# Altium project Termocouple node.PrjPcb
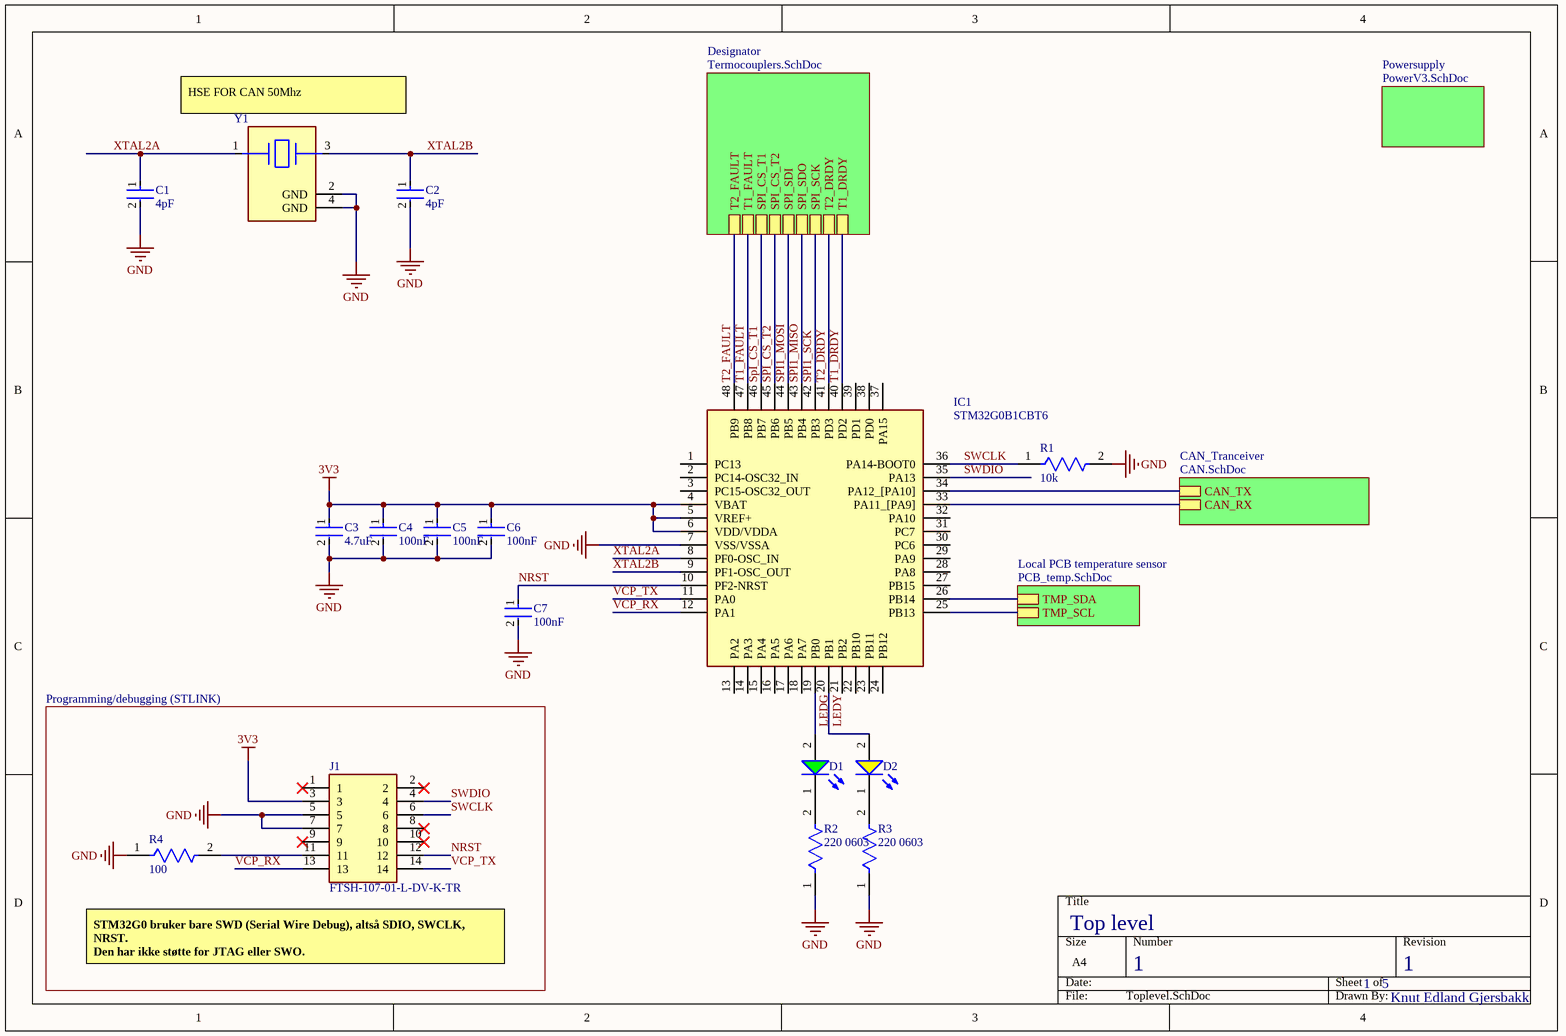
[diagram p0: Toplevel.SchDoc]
5 sheets, 64 parts. Net scope: hierarchical (ports join the sheet entries above them; power ports are global).
Board file: TermoCoupleNode.PcbDoc
Sheets:
  Toplevel.SchDoc
    Powersupply = PowerV3.SchDoc
    CAN_Tranceiver = CAN.SchDoc
    Designator = Termocouplers.SchDoc
    Local PCB temperature sensor = PCB_temp.SchDoc

## Sheet Toplevel.SchDoc
size A4; SheetNumber: 1; SheetTotal: 5

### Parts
C1  4pF  [FP-GQM187-0_15-IPC_B]
C2  4pF  [FP-GQM187-0_15-IPC_B]
C3  4.7uF  [FP-GCM21B-0_15-IPC_A]
C4  100nF  [FP-CL10-IPC_A]
C5  100nF  [FP-CL10-IPC_A]
C6  100nF  [FP-CL10-IPC_A]
C7  100nF  [FP-CL10-IPC_A]
D1  150060GS55040  [WL-SMCD_0603]  (value not drawn)
D2  150060YS75020  [WL-SMCW_0603_150060xx75020]  (value not drawn)
IC1  STM32G0B1CBT6  [QFP50P900X900X160-48N]
J1  FTSH-107-01-L-DV-K-TR  [FTSH10701LDVKTR]
R1  10k  [FP-RT0603-IPC_C]
R2  220 0603  [FP-AF0603-IPC_C]
R3  220 0603  [FP-AF0603-IPC_C]
R4  100  [FP-RT0603-MFG]
Y1  ABM10W-50.0000MHZ-4-B1U-T3  [FP-ABM10W-MFG]  (value not drawn)

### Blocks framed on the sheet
Programming/debugging (STLINK): J1 R4

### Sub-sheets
CAN_Tranceiver = CAN.SchDoc: CAN_TX, CAN_RX
Designator = Termocouplers.SchDoc: T1_FAULT, SPI_SDI, SPI_SDO, SPI_SCK, SPI_CS_T1, T2_DRDY, SPI_CS_T2, T2_FAULT, T1_DRDY
Local PCB temperature sensor = PCB_temp.SchDoc: TMP_SCL, TMP_SDA
Powersupply = PowerV3.SchDoc: no entries

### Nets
3V3: C3.1 C4.1 C5.1 C6.1 IC1.4(VBAT) IC1.5(VREF+) IC1.6(VDD/VDDA) J1.3
GND: C1.2 C2.2 C3.2 C4.2 C5.2 C6.2 C7.2 IC1.7(VSS/VSSA) J1.5 J1.7 R1.2 R2.1 R3.1 R4.1 Y1.2(GND) Y1.4(GND)
LEDG: D1.2(A) IC1.19(PB0)
LEDY: D2.2(A) IC1.20(PB1)
NRST: C7.1 IC1.10(PF2-NRST) J1.12
SCL: IC1.25(PB13) ; sheet Local PCB temperature sensor/TMP_SCL
SDA: IC1.26(PB14) ; sheet Local PCB temperature sensor/TMP_SDA
SPI1_MISO: IC1.43(PB4) ; sheet Designator/SPI_SDO
SPI1_MOSI: IC1.44(PB5) ; sheet Designator/SPI_SDI
SPI1_SCK: IC1.42(PB3) ; sheet Designator/SPI_SCK
SpI_CS_T1: IC1.46(PB7) ; sheet Designator/SPI_CS_T1
SPI_CS_T2: IC1.45(PB6) ; sheet Designator/SPI_CS_T2
SWCLK: IC1.36(PA14-BOOT0) J1.6 R1.1
SWDIO: IC1.35(PA13) J1.4
T1_DRDY: IC1.40(PD2) ; sheet Designator/T1_DRDY
T1_FAULT: IC1.47(PB8) ; sheet Designator/T1_FAULT
T2_DRDY: IC1.41(PD3) ; sheet Designator/T2_DRDY
T2_FAULT: IC1.48(PB9) ; sheet Designator/T2_FAULT
VCP_RX: IC1.12(PA1) J1.13
VCP_TX: IC1.11(PA0) J1.14
XTAL2A: C1.1 IC1.8(PF0-OSC_IN) Y1.1
XTAL2B: C2.1 IC1.9(PF1-OSC_OUT) Y1.3
NetD1_1: D1.1(K) R2.2
NetD2_1: D2.1(K) R3.2
NetIC1_33: IC1.33(PA11_[PA9]) ; sheet CAN_Tranceiver/CAN_RX
NetIC1_34: IC1.34(PA12_[PA10]) ; sheet CAN_Tranceiver/CAN_TX
NetJ1_11: J1.11 R4.2

Not connected (* = marked no-connect by the designer): IC1 1(PC13) 2(PC14-OSC32_IN) 3(PC15-OSC32_OUT) 13(PA2) 14(PA3) 15(PA4) 16(PA5) 17(PA6) 18(PA7) 21(PB2) 22(PB10) 23(PB11) 24(PB12) 27(PB15) 28(PA8) 29(PA9) 30(PC6) 31(PC7) 32(PA10) 37(PA15) 38(PD0) 39(PD1); J1 1* 2* 8* 9* 10*

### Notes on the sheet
- (near Y1) HSE FOR CAN 50Mhz
- Top level
- STM32G0 bruker bare SWD (Serial Wire Debug), altså SDIO, SWCLK, NRST.
  Den har ikke støtte for JTAG eller SWO.
- 1
- 5
- Knut Edland Gjersbakk

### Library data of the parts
C1 C2 = CMP-06035-061124-1: GQM1875C2E4R0BB12D / Ceramic Capacitor 4pF ±0.1pF 250VDC C0G 0603 Paper T/R; Voltage Rating: 250V
C3 = CMP-2007-03343-2: Ceramic Capacitor for Automotive 4.7uF ±10% 16VDC X7R 0805 Embossed T/R; Voltage Rating (DC): 16V
C4-C7 = CMP-13271-002683-1: Cap Ceramic 100nF 16V X7R ±10% Pad SMD 0603 +125°C T/R
D1 = CMP-03913-90235563-2: 150060GS55040 WL-SMCD SMT Mono-color Chip LED Diffused; Forward Voltage: 3.2V; Forward Current: 60mA; Luminous Intensity: 430mcd; Peak Wavelength: 520nm; Viewing Angle: 140°; Wavelength: 525nm; Max Reverse Voltage (DC): 5V
D2 = CMP-03913-104891429-2: WL-SMCW SMT Mono-Color Chip LED Waterclear super f; Forward Voltage: 2V; Forward Current: 60mA; Max Reverse Voltage (DC): 5V; Peak Wavelength: 595nm; Viewing Angle: 140°; Dominant Wavelength: 590nm; Luminous Intensity: 130mcd
IC1 = STM32G0B1CBT6: Integrated Circuit; Manufacturer_Name: STMicroelectronics
J1 = FTSH-107-01-L-DV-K-TR: Connector; Manufacturer_Name: SAMTEC
R1 = CMP-03412-005349-1: RES SMD 10K OHM 1% 1/10W 0603 / RT0603FRE0710KL; Manufacturer: Yageo; Value: 10KΩ; Temperature Coefficient: 50 ppm/°C; Power Rating: 0.1W; Tolerance: 0.01; Voltage Rating: 75V
R2 R3 = CMP-03412-038529-1: AF0603JR-07220RL Anti-Sulfurated Chip Resistors Automotive Grade 220Ω 5% 100ppm/°C 0603; Max Power Dissipation: 100mW; Resistance: 220R
R4 = CMP-03412-030646-1: RT0603 100Ω 0.1W 50 ppm/°C 1.00% RT0603FRE07100RL; Manufacturer: Yageo; Manufacturer Part Number: RT0603FRE10100RL; Tolerance: 0.01; Voltage Rating: 75V
Y1 = CMP-27762-007472-1: Crystal 50MHz ±10ppm 4pF SMD-4 2.5mm x 2mm; ESR (Equivalent Series Resistance): 70R

## Sheet PowerV3.SchDoc
size A3; SheetNumber: 3; SheetTotal: 5
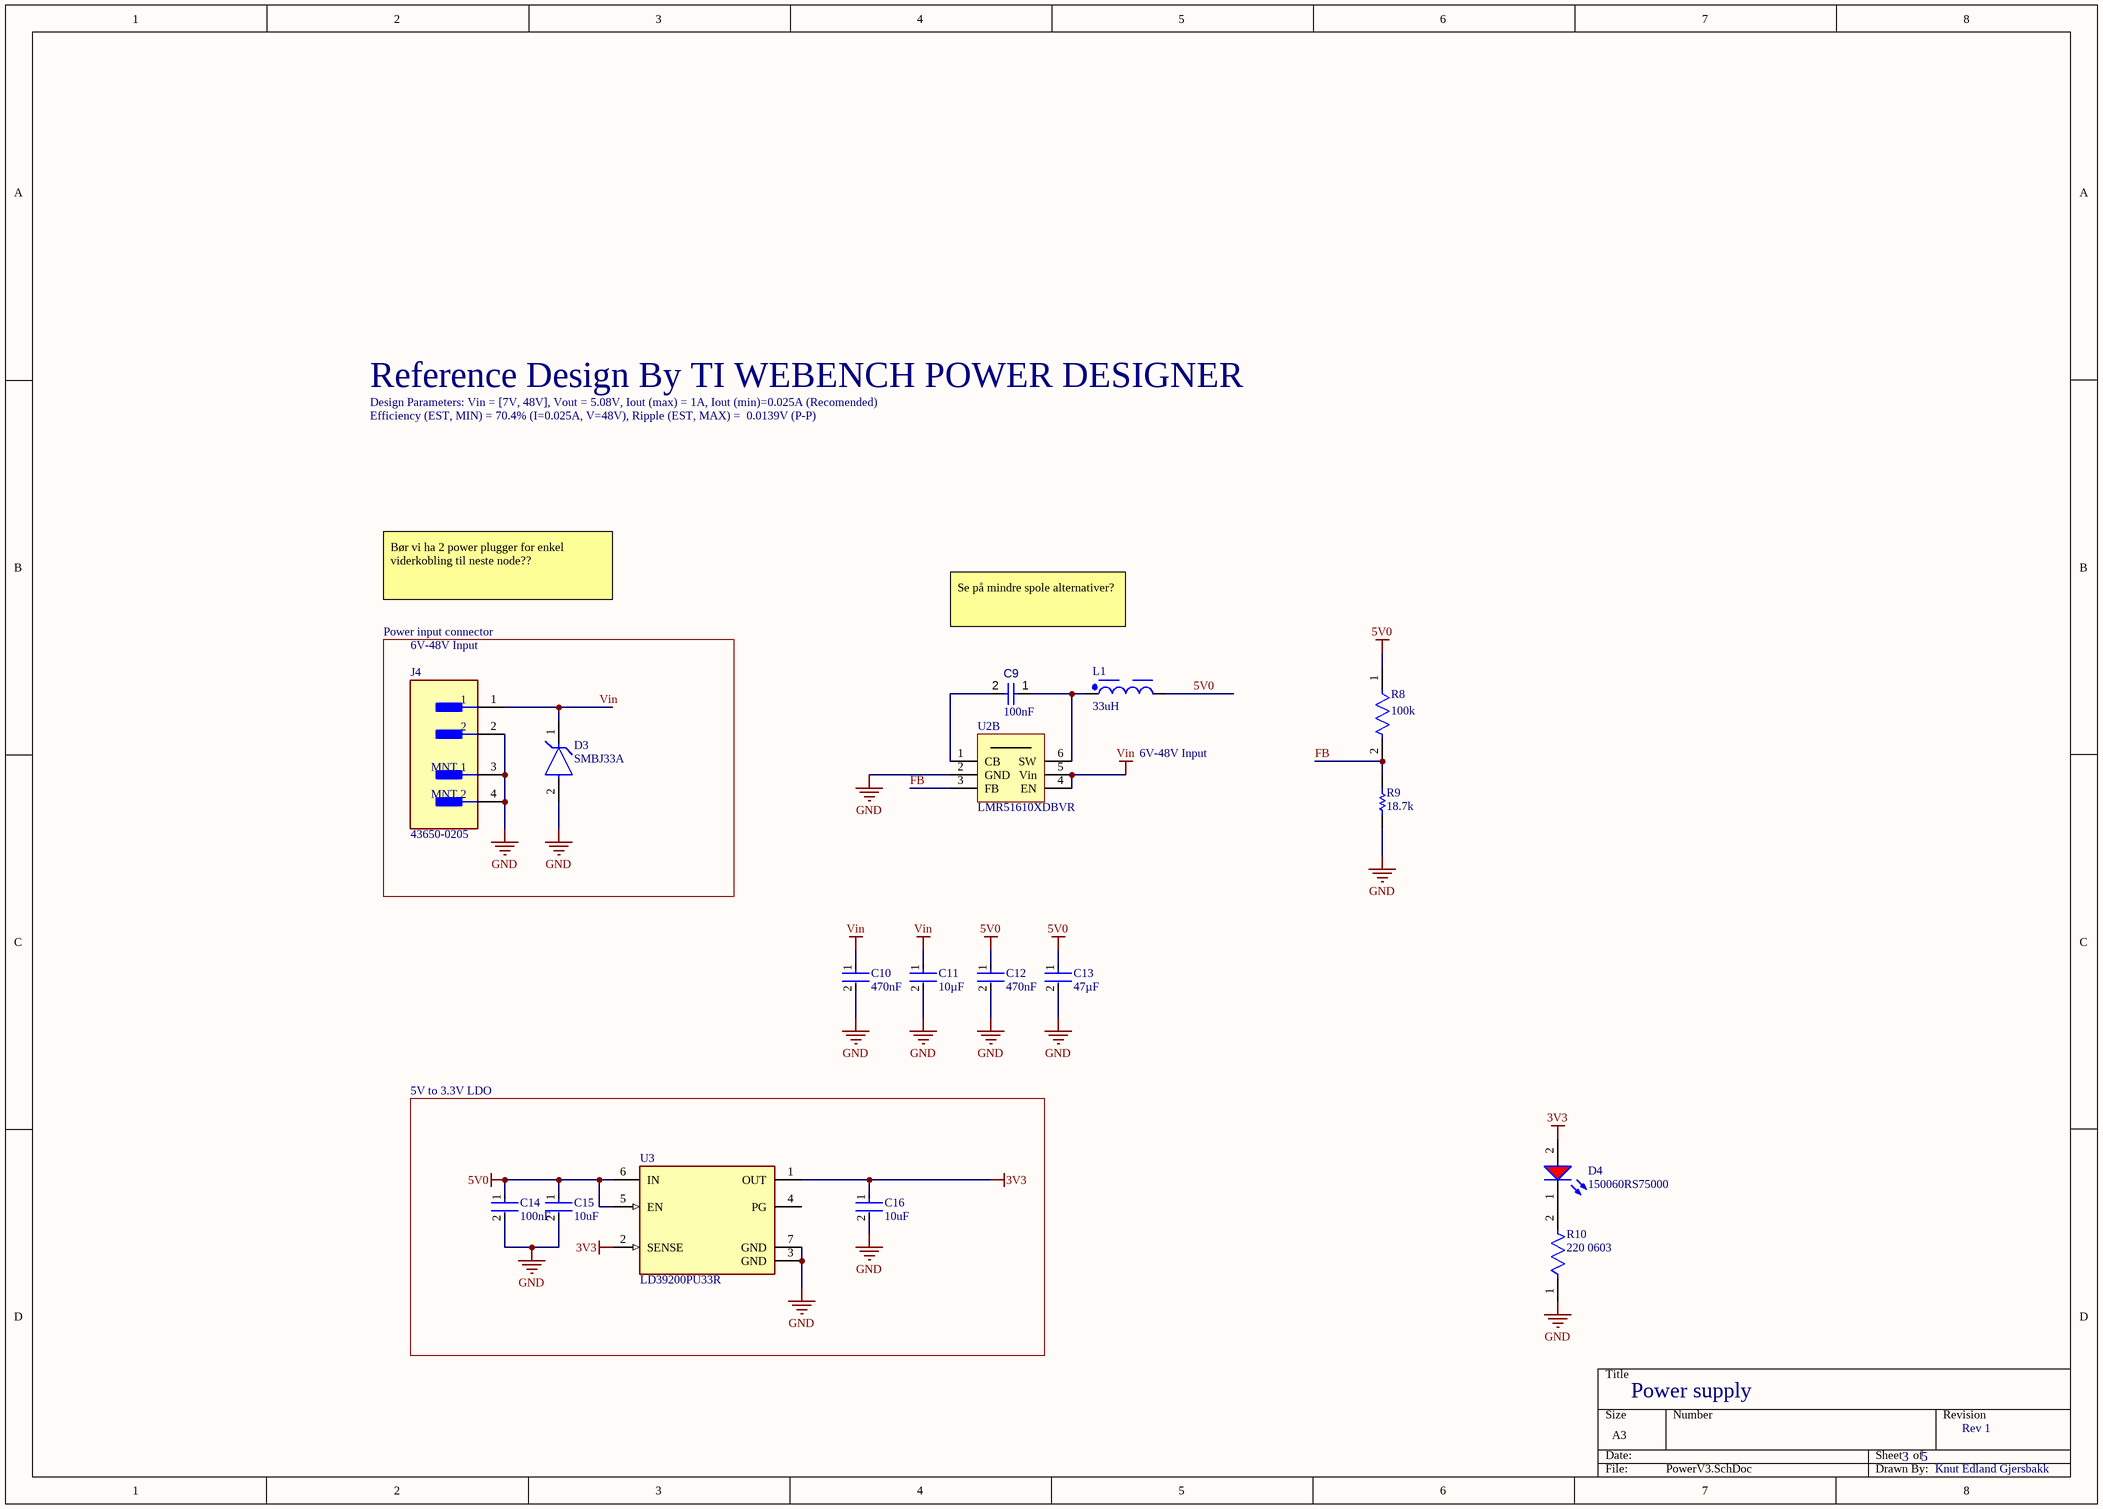
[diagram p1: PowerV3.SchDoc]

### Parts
C9  value 100nF  [CAPC2013X95X50LL10T25]  (hidden comment: Capacitor 100 nF +/-10% 50 V 0805)
C10  value 470nF  [FP-CL21-IPC_A]  (hidden comment: CL21B474KBFNNNF)
C11  value 10µF  [FP-CL31B106KBHNNNE-IPC_A]  (hidden comment: CL31B106KBHNNNE)
C12  value 470nF  [FP-CL21-IPC_A]  (hidden comment: CL21B474KBFNNNF)
C13  value 47µF  [FP-GRM31C-0_2-e0_3_0_8-IPC_B]  (hidden comment: GRM31CR61A476KE15K)
C14  100nF  [FP-CL10-IPC_C]
C15  10uF  [FP-CL10-IPC_C]
C16  10uF  [FP-CL10-IPC_C]
D3  SMBJ33A  [FP-SMBJ-MFG]
D4  150060RS75000  [WL-SMCW_0603_150060xx75000]
J4  43650-0205  [FP-43650-0205-MFG]
L1  value 33uH  [WE-PD_1260P]  (hidden comment: 7447706330)
R8  value 100k  [FP-CRGCQ1206-IPC_A]  (hidden comment: CRGCQ1206F100K)
R9  value 18.7k  [RESC2013X60X40LL20T25]  (hidden comment: ERA-6AEB1872V)
R10  220 0603  [FP-AF0603-IPC_C]
U2  LMR51610XDBVR  [SOT95P280X145-6N]  (part B of 2)
U3  LD39200PU33R  [FP-DFN6-7946637-MFG]

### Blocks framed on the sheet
5V to 3.3V LDO: C14-C16 U3

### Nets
3V3: C16.1 D4.2(A) U3.1(OUT) U3.2(SENSE)
5V0: C12.1 C13.1 C14.1 C15.1 L1.2 R8.1 U3.5(EN) U3.6(IN)
GND: C10.2 C11.2 C12.2 C13.2 C14.2 C15.2 C16.2 D3.2(A) J4.2 J4.3(MNT_1) J4.4(MNT_2) R9.2 R10.1 U2.2(GND) U3.3(GND) U3.7(GND)
Vin: C10.1 C11.1 D3.1(C) J4.1 U2.4(EN) U2.5(Vin)
FB: R8.2 R9.1 U2.3(FB)
NetC9_1: C9.1 L1.1 U2.6(SW)
NetC9_2: C9.2 U2.1(CB)
NetD4_1: D4.1(K) R10.2

Not connected (* = marked no-connect by the designer): U3 4(PG)

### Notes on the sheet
- Reference Design By TI WEBENCH POWER DESIGNER
- Design Parameters: Vin = [7V, 48V], Vout = 5.08V, Iout (max) = 1A, Iout (min)=0.025A (Recomended)
- Efficiency (EST, MIN) = 70.4% (I=0.025A, V=48V), Ripple (EST, MAX) =  0.0139V (P-P)
- Power input connector
- Bør vi ha 2 power plugger for enkel viderkobling til neste node??
- 6V-48V Input
- Se på mindre spole alternativer?
- Power supply
- 3
- 5
- Rev 1
- Knut Edland Gjersbakk

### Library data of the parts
C9 = CMP-001-00018-6: Chip Capacitor, 100 nF, +/- 10%, 50 V, 0805 (2012 Metric); Capacitor Type: Ceramic; Voltage Rating: 50V
C10 C12 = CMP-001-00098-1: Ceramic Capacitor, Multilayer, Ceramic, 50V, 10% +Tol, 10% -Tol, X7R, 15% TC, 0.47uF, Surface Mount, 0805; Multilayer: Yes
C11 = CMP-001-00099-1: Ceramic Capacitor, Multilayer, Ceramic, 50V, 10% +Tol, 10% -Tol, X7R, 15% TC, 10uF, Surface Mount, 1206; Multilayer: Yes
C13 = CMP-001-00103-1: Ceramic Capacitor, Multilayer, Ceramic, 10V, 10% +Tol, 10% -Tol, X5R, 15% TC, 47uF, Surface Mount, 1206; Multilayer: Yes
C14 = CMP-13271-002683-1: Cap Ceramic 100nF 16V X7R ±10% Pad SMD 0603 +125°C T/R / CL10B104KO8WPNC
C15 C16 = CMP-13271-003287-1: Cap Ceramic 10uF 16V X6S ±20% Pad SMD 0603 +105°C T/R / CL10X106MO8NRNC
D3 = CMP-2000-07095-2: TVS DIODE 33V 53.3V DO214AA; Manufacturer: Littelfuse Inc; Max Junction Temp: +150°C; Number Of Channels: 1; Breakdown Voltage: 36.7V; Peak Pulse Power: 600W; Direction: Unidirectional; Peak Pulse Current: 11.3A
D4 = CMP-1426-00001-4: LED Low-Power Uni-Color Red 630nm 2V 2-Pin Chip 0603(1608Metric) T/R; Max Junction Temperature (Tj): 95°C; Dominant Wavelength: 625nm; Lens Style: Clear, Rectangular; Viewing Angle: 140°; Forward Current: 100mA; Max Reverse Voltage (DC): 5V; Luminous Intensity: 250mcd; Test Current: 20mA; Power Dissipation: 72mW
J4 = CMP-00257-07672643-1: 43650-0205 Conn Wire to Board HDR 2 POS 3mm Solder RA Side Entry Thru-Hole Micro-Fit 3.0™ Tray; Manufacturer Lifecycle Status: ACTIVE; Plating: Tin; Glow Wire Compliant: Compliant; Number of Contacts: 2; Gender: Male; Voltage Rating: 600V; Current Rating: 5A
L1 = CMP-006-00028-1: General Purpose Inductor
R8 = CMP-009-00192-1: Fixed Resistor, Metal Glaze/thick Film, 0.25W, 100000ohm, 200V, 1% +/-Tol, 100ppm/Cel, Surface Mount, 1206
R9 = CMP-009-00195-1: Fixed Resistor, Thin Film, 0.125W, 18700ohm, 100V, 0.1% +/-Tol, 25ppm/Cel, Surface Mount, 0805; Rated Temperature: 85°C; Temperature Coefficient (ppm/Cel): 25; Reference Standard: AEC-Q200; Package Width: 1.25mm; Package Length: 2mm; Package Height: 0.5mm; Power: 125mW
R10 = CMP-03412-038529-1: as R2 on sheet Toplevel
U2 = CMP-019-00059-1: SIMPLE SWITCHER® 4.5-V to 65-V, 1-A synchronous buck converter with 25-µA IQ 6-SOT-23 -40 to 150; Max Supply Voltage: 65V; Min Supply Voltage: 4.5V; Output Current: 1A; Frequency: 400Hz
U3 = CMP-12153-000011-1: IC REG LINEAR 3.3V 2A 6DFN; Number of Outputs: 1; Max Input Voltage: 6V; Output Type: Fixed; Min Input Voltage: 1.25V; Dropout Voltage: 130mV; Operating Supply Current: 1mA

## Sheet CAN.SchDoc
size A4; SheetNumber: 2; SheetTotal: 5
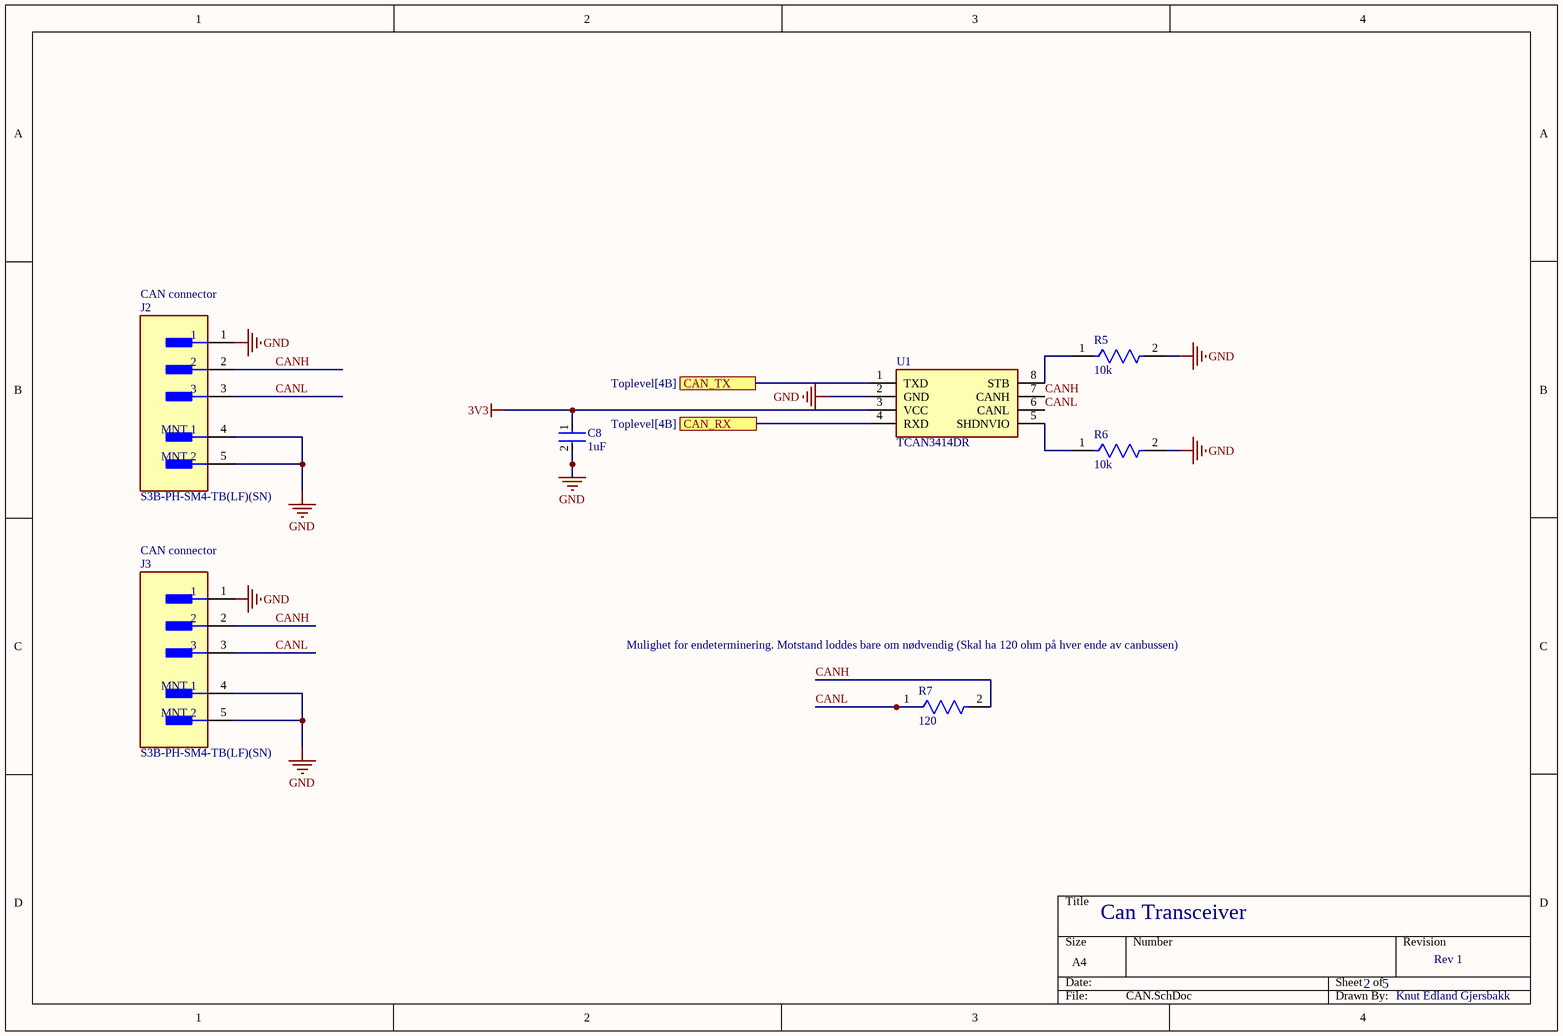
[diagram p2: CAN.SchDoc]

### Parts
C8  1uF  [FP-CL10-IPC_C]
J2  S3B-PH-SM4-TB(LF)(SN)  [FP-S3B-PH-SM4-TB_LF_SN-MFG]
J3  S3B-PH-SM4-TB(LF)(SN)  [FP-S3B-PH-SM4-TB_LF_SN-MFG]
R5  10k  [FP-RT0603-IPC_C]
R6  10k  [FP-RT0603-IPC_C]
R7  120  [FP-AF0603-IPC_C]
U1  TCAN3414DR  [SOIC127P600X175-8N]

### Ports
CAN_RX (see Toplevel[4B]), CAN_TX (see Toplevel[4B])

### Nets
3V3: C8.1 U1.3(VCC)
GND: C8.2 J2.1 J2.4(MNT_1) J2.5(MNT_2) J3.1 J3.4(MNT_1) J3.5(MNT_2) R5.2 R6.2 U1.2(GND)
CANH: J2.2 J3.2 R7.2 U1.7(CANH)
CANL: J2.3 J3.3 R7.1 U1.6(CANL)
NetIC1_33: U1.4(RXD) ; port CAN_RX
NetIC1_34: U1.1(TXD) ; port CAN_TX
NetR5_1: R5.1 U1.8(STB)
NetR6_1: R6.1 U1.5(SHDNVIO)

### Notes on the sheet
- (near J2) CAN connector
- (near J3) CAN connector
- Mulighet for endeterminering. Motstand loddes bare om nødvendig (Skal ha 120 ohm på hver ende av canbussen)
- Can Transceiver
- 2
- 5
- Rev 1
- Knut Edland Gjersbakk

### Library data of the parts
C8 = CMP-13271-000784-1: Cap Ceramic 1uF 16V X7R ±10% Pad SMD 0603 +125°C T/R / CL10B105KO8NNNL
J2 J3 = CMP-002-00113-1: Connector Header, PH Series, 3 Position, Side Entry, 2.00mm, Solder, Surface Mount, Natural.; Voltage Rating: 100V; Max Current Rating: 2A; Connector Type: Male Pin; Gender: Male
R5 R6 = CMP-03412-005349-1: as R1 on sheet Toplevel
R7 = CMP-03412-039700-1: Anti-Sulfurated Chip Resistors Automotive Grade 120Ω 1% 100ppm/°C 0603 AF0603FR-07120RL; Max Power Dissipation: 100mW; Resistance: 120R
U1 = TCAN3414DR: Integrated Circuit; Manufacturer_Name: Texas Instruments

## Sheet Termocouplers.SchDoc
size A3; SheetNumber: 5; SheetTotal: 5
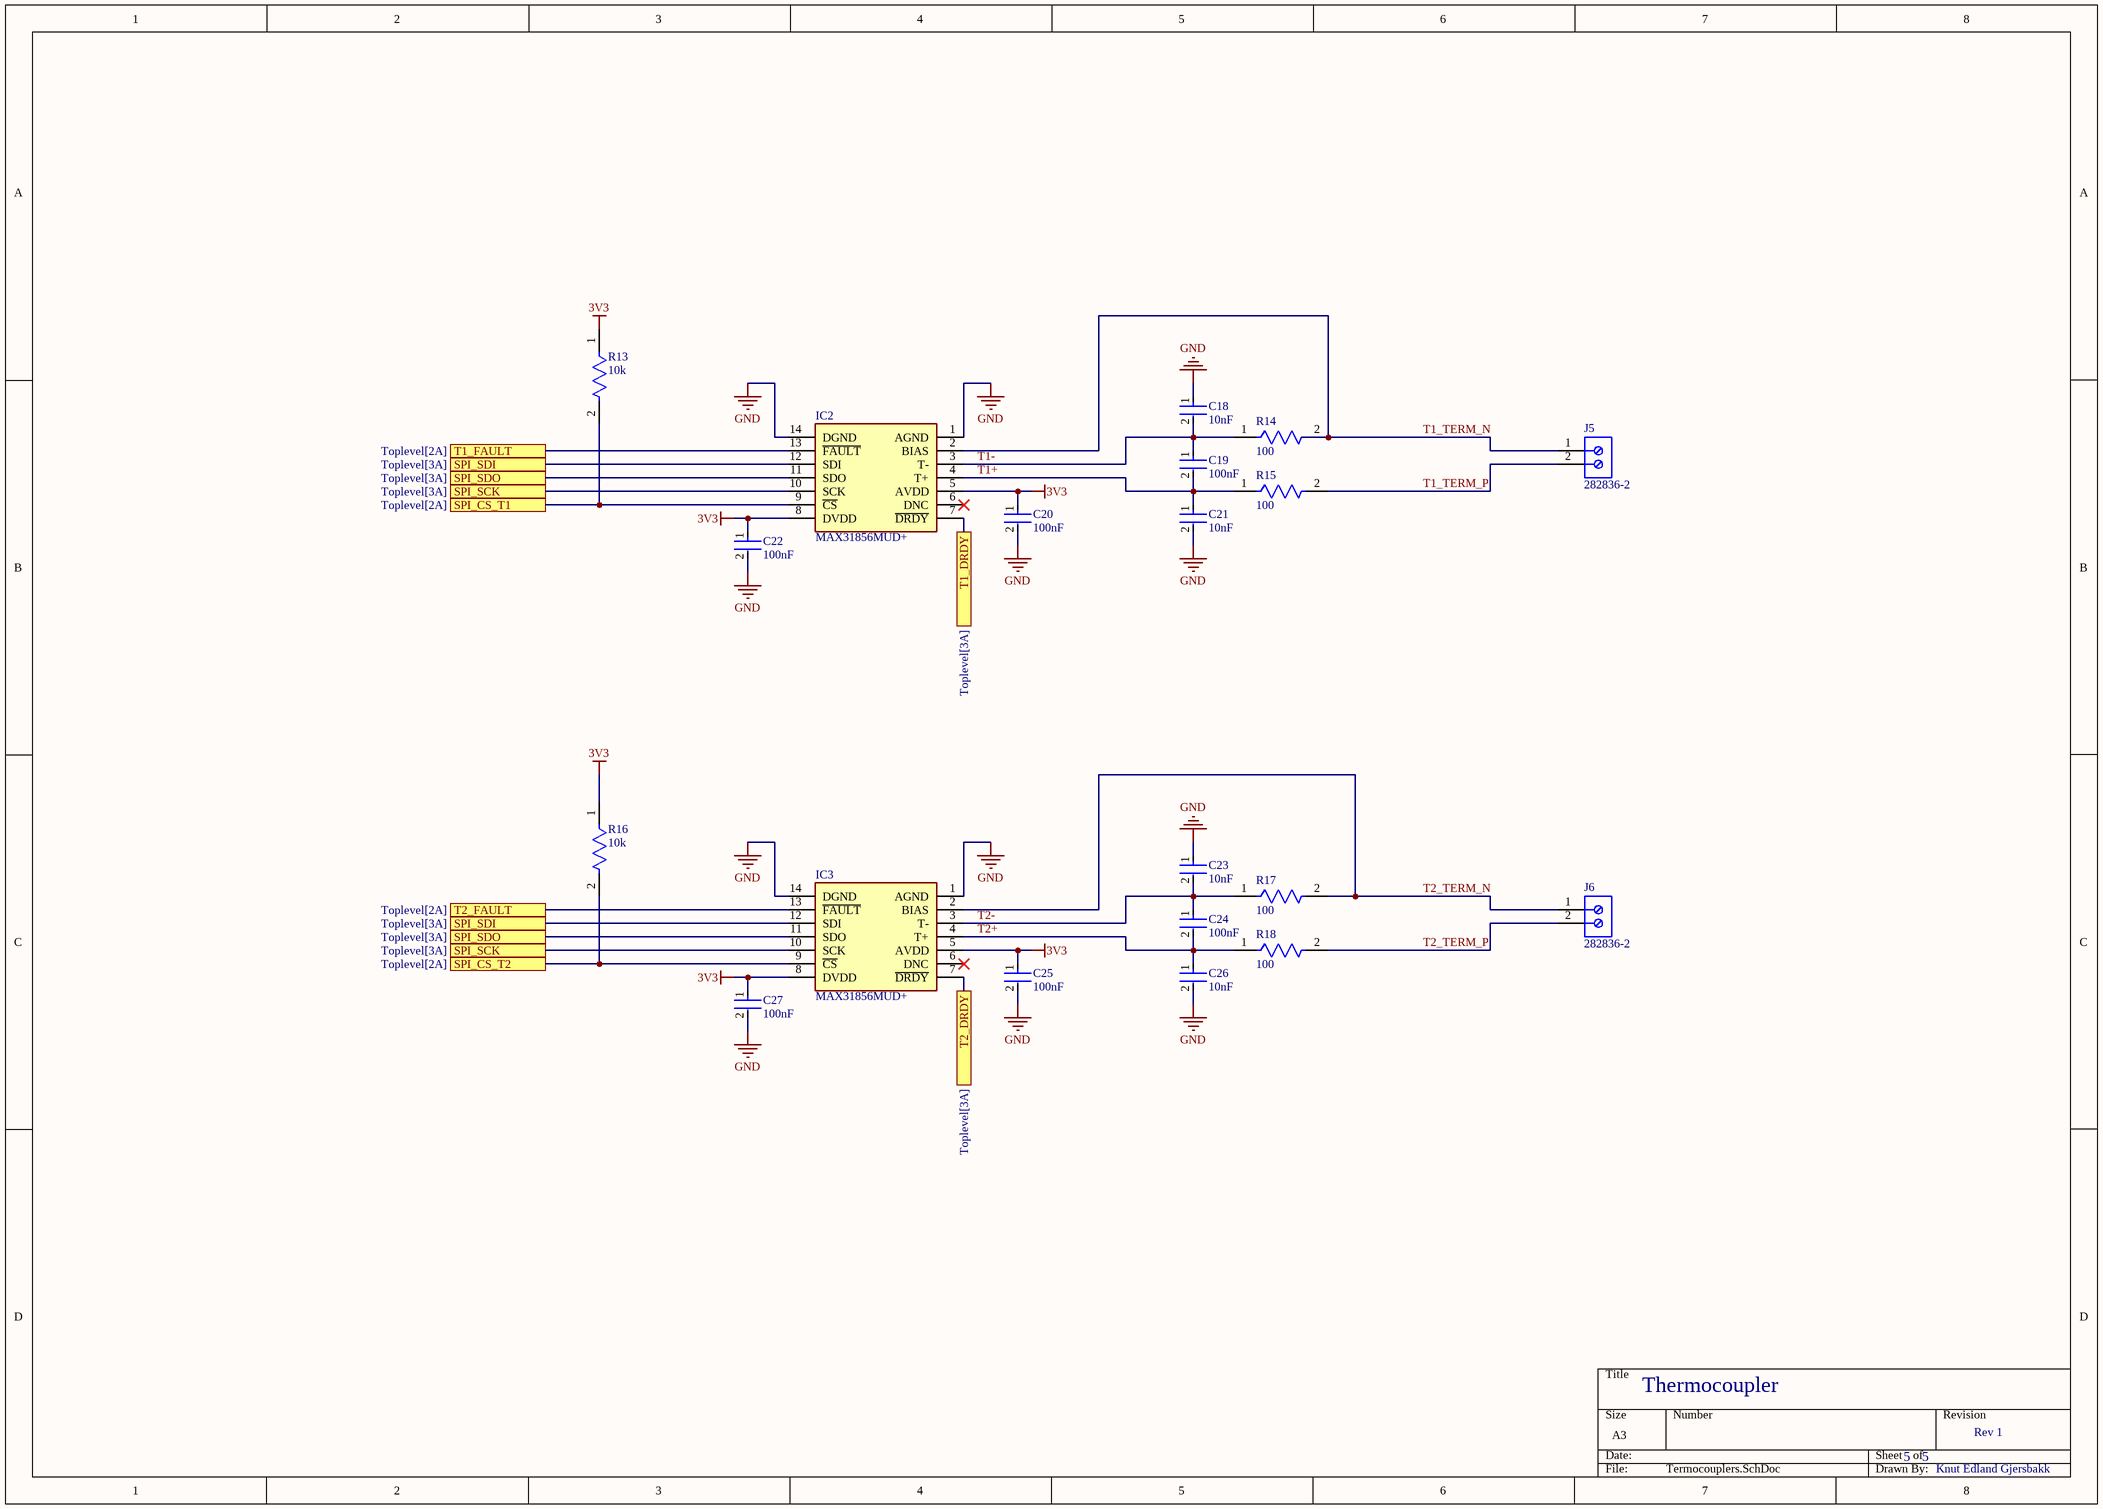
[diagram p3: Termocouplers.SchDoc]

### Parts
C18  10nF  [FP-GCM188-0_1-MFG]
C19  100nF  [FP-GCM188-0_1-IPC_B]
C20  100nF  [FP-GCM188-0_1-IPC_B]
C21  10nF  [FP-GCM188-0_1-MFG]
C22  100nF  [FP-GCM188-0_1-IPC_B]
C23  10nF  [FP-GCM188-0_1-MFG]
C24  100nF  [FP-GCM188-0_1-IPC_B]
C25  100nF  [FP-GCM188-0_1-IPC_B]
C26  10nF  [FP-GCM188-0_1-MFG]
C27  100nF  [FP-GCM188-0_1-IPC_B]
IC2  MAX31856MUD+  [SOP65P640X110-14N]
IC3  MAX31856MUD+  [SOP65P640X110-14N]
J5  282836-2  [TECO-282836-2_V]
J6  282836-2  [TECO-282836-2_V]
R13  10k  [FP-RT0603-IPC_C]
R14  100  [FP-CR0603-IPC_A]
R15  100  [FP-CR0603-IPC_A]
R16  10k  [FP-RT0603-IPC_C]
R17  100  [FP-CR0603-IPC_A]
R18  100  [FP-CR0603-IPC_A]

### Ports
SPI_CS_T1 (see Toplevel[2A]), SPI_CS_T2 (see Toplevel[2A]), SPI_SCK (see Toplevel[3A]), SPI_SDI (see Toplevel[3A]), SPI_SDO (see Toplevel[3A]), T1_DRDY (see Toplevel[3A]), T1_FAULT (see Toplevel[2A]), T2_DRDY (see Toplevel[3A]), T2_FAULT (see Toplevel[2A])

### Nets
3V3: C20.1 C22.1 C25.1 C27.1 IC2.5(AVDD) IC2.8(DVDD) IC3.5(AVDD) IC3.8(DVDD) R13.1 R16.1
GND: C18.1 C20.2 C21.2 C22.2 C23.1 C25.2 C26.2 C27.2 IC2.1(AGND) IC2.14(DGND) IC3.1(AGND) IC3.14(DGND)
SPI1_MISO: IC2.11(SDO) IC3.11(SDO) ; port SPI_SDO
SPI1_MOSI: IC2.12(SDI) IC3.12(SDI) ; port SPI_SDI
SPI1_SCK: IC2.10(SCK) IC3.10(SCK) ; port SPI_SCK
SpI_CS_T1: IC2.9(~{CS}) R13.2 ; port SPI_CS_T1
SPI_CS_T2: IC3.9(~{CS}) R16.2 ; port SPI_CS_T2
T1+: C19.2 C21.1 IC2.4(T+) R15.1
T1-: C18.2 C19.1 IC2.3(T-) R14.1
T1_DRDY: IC2.7(~{DRDY}) ; port T1_DRDY
T1_FAULT: IC2.13(~{FAULT}) ; port T1_FAULT
T1_TERM_N: IC2.2(BIAS) J5.1 R14.2
T1_TERM_P: J5.2 R15.2
T2+: C24.2 C26.1 IC3.4(T+) R18.1
T2-: C23.2 C24.1 IC3.3(T-) R17.1
T2_DRDY: IC3.7(~{DRDY}) ; port T2_DRDY
T2_FAULT: IC3.13(~{FAULT}) ; port T2_FAULT
T2_TERM_N: IC3.2(BIAS) J6.1 R17.2
T2_TERM_P: J6.2 R18.2

Not connected (* = marked no-connect by the designer): IC2 6(DNC)*; IC3 6(DNC)*

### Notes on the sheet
- Thermocoupler
- 5
- Rev 1
- Knut Edland Gjersbakk

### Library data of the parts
C18 C21 C23 C26 = CMP-2006-02392-2: Ceramic Capacitor for Automotive 10nF  ±10% 100VDC X7R 0603 Paper T/R; Voltage: 100V
C19 C20 C22 C24 C25 C27 = CMP-2006-02353-3: Ceramic Capacitor for Automotive 100nF  ±10% 50VDC X8L 0603 Paper T/R; Voltage Rating: 50V
IC2 IC3 = MAX31856MUD+: Integrated Circuit; Manufacturer_Name: Analog Devices
J5 J6 = CMP-1684-00017-1: Female Header, Pitch 5 mm, 1 x 2 Position, Height 10 mm, Tail Length 3.5 mm, Rohs, Bulk; Manufacturer: TE Connectivity; Wire Gauge: 16-30AWG; Product Training Modules: Wire-to-BoardEurostyleTerminalBlocks; Clamp Material - Plating: Brass-NickelPlated; Voltage: 300V; Mating Orientation: HorizontalwithBoard; Current: 13.5A; Pitch: 0.197"(5.00mm); Screw Thread: M3; 3D Model: 282836-2.pdf; Other Names: 5ULV-02B / A98076; Dynamic Catalog: BuchananSeries; Number of Levels: 1; Torque - Screw: 0.68Nm(6Lb-In); Featured Product: EurostyleTerminalBlockConnectors; Positions Per Level: 2; Wire Termination: Screw-RisingCageClamp
R13 R16 = CMP-03412-005349-1: as R1 on sheet Toplevel
R14 R15 R17 R18 = CMP-07231-000376-1: AEC-Q200 Compliant Chip Resistors 0603 100Ω 0.1W 1% 100ppm/°C

## Sheet PCB_temp.SchDoc
size A4; SheetNumber: 4; SheetTotal: 5
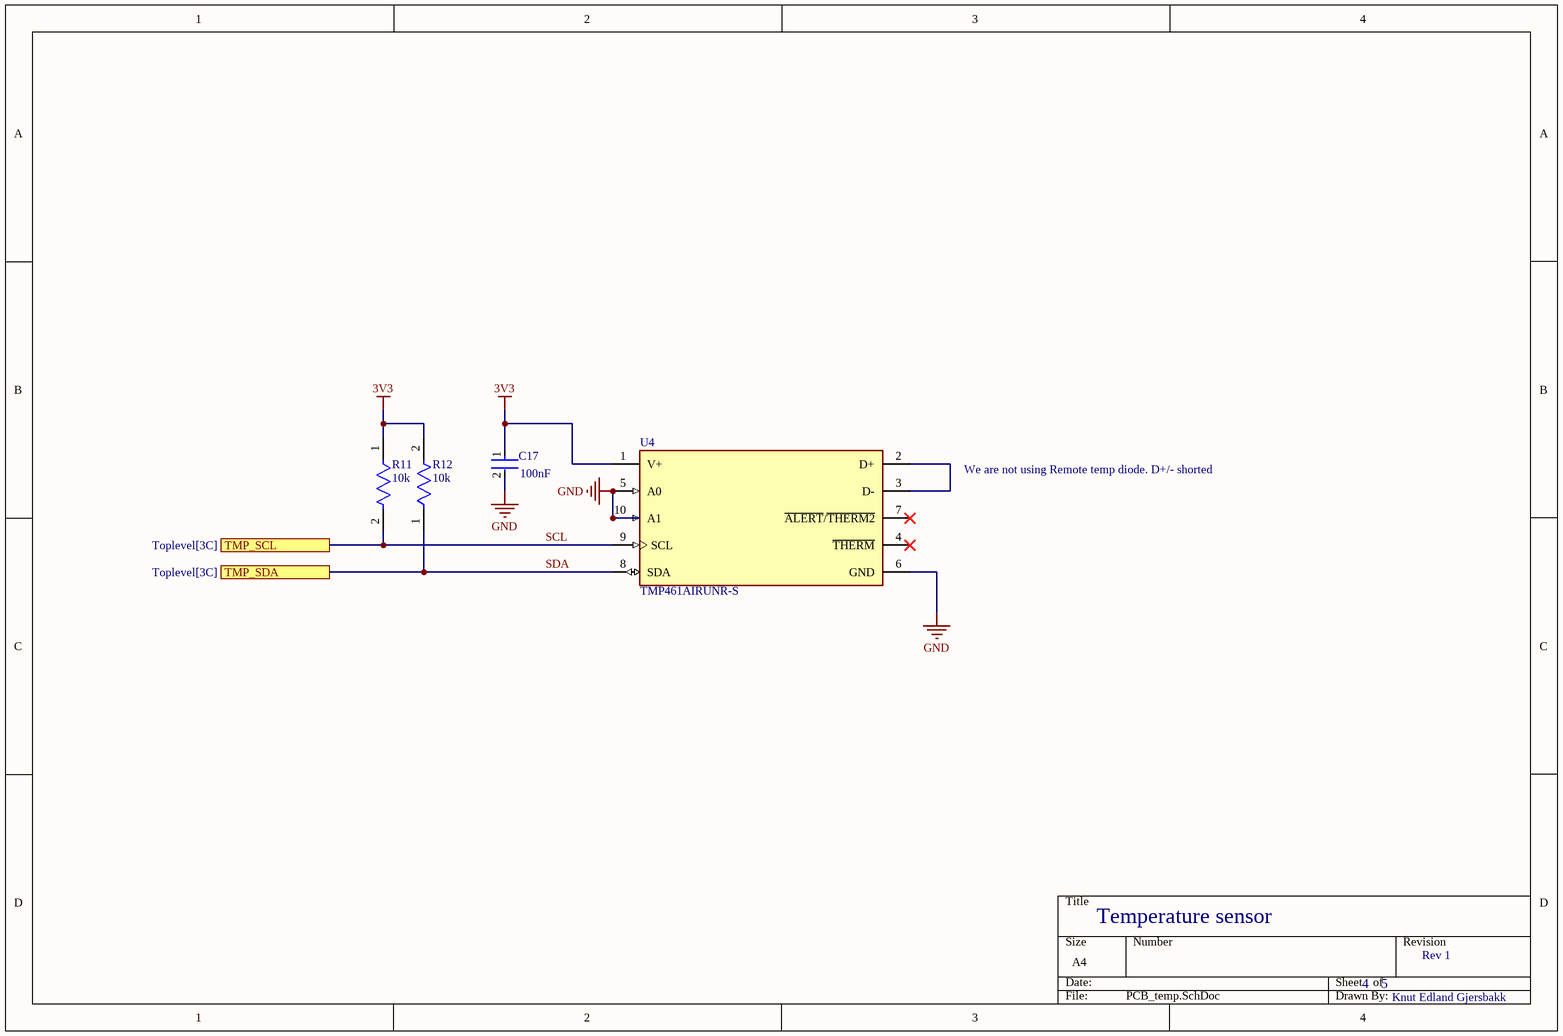
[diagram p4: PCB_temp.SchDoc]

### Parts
C17  100nF  [FP-CL10-IPC_A]
R11  10k  [FP-RT0603-IPC_C]
R12  10k  [FP-RT0603-IPC_C]
U4  TMP461AIRUNR-S  [FP-RUN0010A-MFG]

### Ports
TMP_SCL (see Toplevel[3C]), TMP_SDA (see Toplevel[3C])

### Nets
3V3: C17.1 R11.1 R12.2 U4.1(V+)
GND: C17.2 U4.5(A0) U4.6(GND) U4.10(A1)
SCL: R11.2 U4.9(SCL) ; port TMP_SCL
SDA: R12.1 U4.8(SDA) ; port TMP_SDA
NetU4_2: U4.2(D+) U4.3(D-)

Not connected (* = marked no-connect by the designer): U4 4(~{THERM})* 7(~{ALERT}/~{THERM2})*

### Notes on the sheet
- We are not using Remote temp diode. D+/- shorted
- Temperature sensor
- 4
- 5
- Rev 1
- Knut Edland Gjersbakk

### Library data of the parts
C17 = CMP-13271-002683-1: as C4 on sheet Toplevel
R11 R12 = CMP-03412-005349-1: as R1 on sheet Toplevel
U4 = CMP-00370-103943066-1: TMP461AIRUNR-S Temperature Sensor Digital, Local/Remote -40°C ~ 125°C 11 b 10-WQFN (2x2); Manufacturer Lifecycle Status: ACTIVE

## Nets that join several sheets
3V3: Toplevel (8 pins), PowerV3 (C16.1 D4.2 U3.1 U3.2), CAN (C8.1 U1.3), Termocouplers (10 pins), PCB_temp (C17.1 R11.1 R12.2 U4.1)
GND: Toplevel (16 pins), PowerV3 (16 pins), CAN (10 pins), Termocouplers (12 pins), PCB_temp (C17.2 U4.5 U4.6 U4.10)
NetIC1_33: Toplevel (IC1.33), CAN (U1.4)
NetIC1_34: Toplevel (IC1.34), CAN (U1.1)
SCL: Toplevel (IC1.25), PCB_temp (R11.2 U4.9)
SDA: Toplevel (IC1.26), PCB_temp (R12.1 U4.8)
SPI1_MISO: Toplevel (IC1.43), Termocouplers (IC2.11 IC3.11)
SPI1_MOSI: Toplevel (IC1.44), Termocouplers (IC2.12 IC3.12)
SPI1_SCK: Toplevel (IC1.42), Termocouplers (IC2.10 IC3.10)
SpI_CS_T1: Toplevel (IC1.46), Termocouplers (IC2.9 R13.2)
SPI_CS_T2: Toplevel (IC1.45), Termocouplers (IC3.9 R16.2)
T1_DRDY: Toplevel (IC1.40), Termocouplers (IC2.7)
T1_FAULT: Toplevel (IC1.47), Termocouplers (IC2.13)
T2_DRDY: Toplevel (IC1.41), Termocouplers (IC3.7)
T2_FAULT: Toplevel (IC1.48), Termocouplers (IC3.13)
